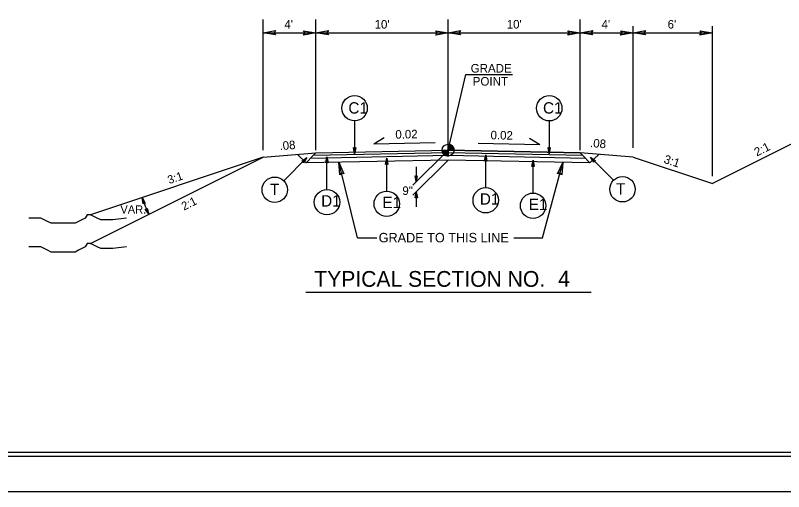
# Model space of a CAD drawing. Extents: x 573771 to 574316, y -53454 to -53190.
# Drawn here: x 574083 to 574199.3, y -53453.5 to -53381.4 of the extents above; entities that cross this region are included whole.
import ezdxf

# ---------------------------------------------------------------- set-up
doc = ezdxf.new("R2010")
doc.units = 0
for name, color, linetype in [('Sheet Cutting Line CELL', 7, 'Continuous'), ('Sheet Plot Border Inside CELL', 7, 'Continuous'), ('Sheet Plot Border Outside CELL', 7, 'Continuous'), ('Sheet Typical CELL', 7, 'Continuous'), ('Typical Grade Point Symbol CELL', 7, 'Continuous'), ('Typical ID Circle CELL', 7, 'Continuous'), ('Typical Pavement Slope CELL', 7, 'Continuous'), ('Typical Pavement Slope Information CELL', 7, 'Continuous'), ('Typical Shoulder Slope CELL', 7, 'Continuous'), ('Typical Shoulder Slope Information CELL', 7, 'Continuous'), ('Typical Slope Point Local CELL', 7, 'Continuous'), ('Typical Terminator CELL', 7, 'Continuous'), ('Typical Text General CELL', 7, 'Continuous'), ('Typical Text Grade Point CELL', 7, 'Continuous'), ('Typical Text ID Circle CELL', 7, 'Continuous'), ('Typical Text Label CELL', 7, 'Continuous')]:
    doc.layers.add(name, color=color, linetype=linetype)

msp = doc.modelspace()

# ---------------------------------------------------------------- linework, layer by layer
at = {"layer": 'Sheet Cutting Line CELL'}
msp.add_line((573911.95, -53453.54), (574316.11, -53453.54), dxfattribs=at)
at = {"layer": 'Sheet Plot Border Inside CELL'}
msp.add_lwpolyline([(574315.03, -53194.93), (573915.07, -53194.93), (573915.07, -53448.15), (574315.03, -53448.15)], close=True, dxfattribs=at)
at = {"layer": 'Sheet Plot Border Outside CELL'}
msp.add_lwpolyline([(574316.11, -53189.54), (573911.95, -53189.54), (573911.95, -53453.54), (574316.11, -53453.54)], close=True, dxfattribs=at)
at = {"layer": 'Sheet Typical CELL'}
msp.add_lwpolyline([(574312.03, -53195.54), (573952.03, -53195.54), (573952.03, -53447.54), (574312.03, -53447.54)], close=True, dxfattribs=at)
at = {"layer": 'Typical Grade Point Symbol CELL'}
for p, q in [((574148.51, -53401.82), (574148.51, -53400.93)), ((574147.62, -53401.82), (574148.51, -53401.82)), ((574149.41, -53401.82), (574148.51, -53401.82)), ((574148.51, -53402.72), (574148.51, -53401.82)), ((574148.51, -53401.82), (574148.51, -53402.72))]:
    msp.add_line(p, q, dxfattribs=at)
for points in [[(574148.52, -53400.93), (574148.52, -53400.93), (574148.52, -53401.82)], [(574148.54, -53400.93), (574148.54, -53401.82)], [(574148.56, -53400.93), (574148.56, -53401.82)], [(574148.57, -53400.93), (574148.57, -53401.82)], [(574148.59, -53400.93), (574148.59, -53401.82)], [(574148.61, -53400.93), (574148.61, -53401.82)], [(574148.63, -53400.93), (574148.63, -53401.82)], [(574148.64, -53400.94), (574148.64, -53401.82)], [(574148.66, -53400.94), (574148.66, -53401.82)], [(574148.68, -53400.94), (574148.68, -53401.82)], [(574148.7, -53400.95), (574148.7, -53401.82)], [(574148.72, -53400.95), (574148.72, -53401.82)], [(574148.73, -53400.95), (574148.73, -53401.82)], [(574148.75, -53400.96), (574148.75, -53401.82)], [(574148.77, -53400.96), (574148.77, -53401.82)], [(574148.79, -53400.97), (574148.79, -53401.82)], [(574148.81, -53400.98), (574148.81, -53401.82)], [(574148.82, -53400.98), (574148.82, -53401.82)], [(574148.84, -53400.99), (574148.84, -53401.82)], [(574148.86, -53401), (574148.86, -53401.82)], [(574148.88, -53401.01), (574148.88, -53401.82)], [(574148.9, -53401.01), (574148.9, -53401.82)], [(574148.91, -53401.02), (574148.91, -53401.82)], [(574148.93, -53401.03), (574148.93, -53401.82)], [(574148.95, -53401.04), (574148.95, -53401.82)], [(574148.97, -53401.05), (574148.97, -53401.82)], [(574148.98, -53401.06), (574148.98, -53401.82)], [(574149, -53401.07), (574149, -53401.82)], [(574149.02, -53401.09), (574149.02, -53401.82)], [(574149.04, -53401.1), (574149.04, -53401.82)], [(574149.06, -53401.11), (574149.06, -53401.82)], [(574149.07, -53401.12), (574149.07, -53401.82)], [(574149.09, -53401.14), (574149.09, -53401.82)], [(574149.11, -53401.16), (574149.11, -53401.82)], [(574149.13, -53401.17), (574149.13, -53401.82)], [(574149.15, -53401.19), (574149.15, -53401.82)], [(574149.16, -53401.21), (574149.16, -53401.82)], [(574149.18, -53401.23), (574149.18, -53401.82)], [(574149.2, -53401.25), (574149.2, -53401.82)], [(574149.22, -53401.27), (574149.22, -53401.82)], [(574149.24, -53401.3), (574149.24, -53401.82)], [(574149.25, -53401.32), (574149.25, -53401.82)], [(574149.27, -53401.35), (574149.27, -53401.82)], [(574149.29, -53401.38), (574149.29, -53401.82)], [(574149.31, -53401.41), (574149.31, -53401.82)], [(574149.33, -53401.45), (574149.33, -53401.82)], [(574147.62, -53401.82), (574147.62, -53401.92)], [(574147.64, -53401.82), (574147.64, -53402.02)], [(574147.66, -53401.82), (574147.66, -53402.09)], [(574147.67, -53401.82), (574147.67, -53402.14)], [(574147.69, -53401.82), (574147.69, -53402.18)], [(574147.71, -53401.82), (574147.71, -53402.22)], [(574147.73, -53401.82), (574147.73, -53402.25)], [(574147.75, -53401.82), (574147.75, -53402.29)], [(574147.76, -53401.82), (574147.76, -53402.31)], [(574147.78, -53401.82), (574147.78, -53402.34)], [(574147.8, -53401.82), (574147.8, -53402.36)], [(574147.82, -53401.82), (574147.82, -53402.39)], [(574147.84, -53401.82), (574147.84, -53402.41)], [(574147.85, -53401.82), (574147.85, -53402.43)], [(574147.87, -53401.82), (574147.87, -53402.45)], [(574147.89, -53401.82), (574147.89, -53402.47)], [(574147.91, -53401.82), (574147.91, -53402.48)], [(574147.92, -53401.82), (574147.92, -53402.5)], [(574147.94, -53401.82), (574147.94, -53402.51)], [(574147.96, -53401.82), (574147.96, -53402.53)], [(574147.98, -53401.82), (574147.98, -53402.54)], [(574148, -53401.82), (574148, -53402.55)], [(574148.01, -53401.82), (574148.01, -53402.56)], [(574148.03, -53401.82), (574148.03, -53402.58)], [(574148.05, -53401.82), (574148.05, -53402.59)], [(574148.07, -53401.82), (574148.07, -53402.6)], [(574148.09, -53401.82), (574148.09, -53402.61)], [(574148.1, -53401.82), (574148.1, -53402.62)], [(574148.12, -53401.82), (574148.12, -53402.63)], [(574148.14, -53401.82), (574148.14, -53402.63)], [(574148.16, -53401.82), (574148.16, -53402.64)], [(574148.18, -53401.82), (574148.18, -53402.65)], [(574148.19, -53401.82), (574148.19, -53402.66)], [(574148.21, -53401.82), (574148.21, -53402.66)], [(574148.23, -53401.82), (574148.23, -53402.67)], [(574148.25, -53401.82), (574148.25, -53402.68)], [(574148.26, -53401.82), (574148.26, -53402.68)], [(574148.28, -53401.82), (574148.28, -53402.69)], [(574148.3, -53401.82), (574148.3, -53402.69)], [(574148.32, -53401.82), (574148.32, -53402.69)], [(574148.34, -53401.82), (574148.34, -53402.7)], [(574148.35, -53401.82), (574148.35, -53402.7)], [(574148.37, -53401.82), (574148.37, -53402.7)], [(574148.39, -53401.82), (574148.39, -53402.71)], [(574148.41, -53401.82), (574148.41, -53402.71)], [(574148.43, -53401.82), (574148.43, -53402.71)], [(574148.44, -53401.82), (574148.44, -53402.71)], [(574148.46, -53401.82), (574148.46, -53402.71)], [(574148.48, -53401.82), (574148.48, -53402.72)], [(574148.5, -53401.82), (574148.5, -53402.72), (574148.5, -53402.72)], [(574149.34, -53401.49), (574149.34, -53401.82)], [(574149.36, -53401.54), (574149.36, -53401.82)], [(574149.38, -53401.6), (574149.38, -53401.82)], [(574149.4, -53401.69), (574149.4, -53401.82)]]:
    msp.add_lwpolyline(points, dxfattribs=at)
msp.add_circle((574148.51, -53401.82), 0.895, dxfattribs=at)
for start, end in [(359.9905, 89.9905), (179.9905, 269.9905)]:
    msp.add_arc((574148.51, -53401.82), 0.895, start, end, dxfattribs=at)
at = {"layer": 'Typical ID Circle CELL'}
for p, q in [((574134.36, -53397.4), (574134.36, -53402.37)), ((574163.82, -53397.4), (574163.82, -53402.37)), ((574154.2, -53407.5), (574154.2, -53402.52)), ((574123.63, -53406.46), (574127.15, -53402.95)), ((574130.18, -53407.79), (574130.18, -53402.82)), ((574139.22, -53408.03), (574139.22, -53403.06)), ((574161.37, -53408.32), (574161.37, -53403.35)), ((574173.55, -53406.39), (574170.04, -53402.88))]:
    msp.add_line(p, q, dxfattribs=at)
for centre in [(574134.36, -53395.47), (574163.82, -53395.48), (574122.27, -53407.82), (574174.91, -53407.75), (574130.18, -53409.71), (574139.22, -53409.95), (574154.2, -53409.42), (574161.37, -53410.24)]:
    msp.add_circle(centre, 1.92, dxfattribs=at)
at = {"layer": 'Typical Pavement Slope CELL'}
for p in [(574128.51, -53402.22), (574168.51, -53402.22)]:
    msp.add_line(p, (574148.51, -53401.82), dxfattribs=at)
at = {"layer": 'Typical Pavement Slope Information CELL'}
for p, q in [((574120.51, -53401.82), (574120.51, -53382.05)), ((574128.51, -53401.82), (574128.51, -53382.05)), ((574148.51, -53401.82), (574148.51, -53382.05)), ((574168.51, -53401.82), (574168.51, -53382.05)), ((574176.51, -53401.46), (574176.51, -53383.05)), ((574188.51, -53405.77), (574188.51, -53383.05)), ((574120.51, -53384.05), (574128.51, -53384.05)), ((574128.51, -53384.05), (574148.51, -53384.05)), ((574148.51, -53384.05), (574168.51, -53384.05)), ((574168.51, -53384.05), (574176.51, -53384.05)), ((574176.51, -53384.05), (574188.51, -53384.05)), ((574137.25, -53400.85), (574138.82, -53399.91)), ((574162.39, -53401.03), (574160.82, -53400.08)), ((574137.25, -53400.85), (574146.57, -53400.67)), ((574162.39, -53401.03), (574153.07, -53400.84)), ((574125.69, -53402.46), (574127.04, -53403.75)), ((574128.1, -53402.65), (574128.51, -53402.22)), ((574148.51, -53402.24), (574128.1, -53402.65)), ((574128.51, -53402.22), (574148.51, -53401.82)), ((574143.19, -53407.14), (574148.51, -53401.82)), ((574148.51, -53401.82), (574168.51, -53402.22)), ((574168.92, -53402.65), (574148.51, -53402.24)), ((574168.51, -53402.22), (574168.92, -53402.65)), ((574171.33, -53402.46), (574169.98, -53403.75)), ((574127.04, -53403.75), (574128.1, -53402.65)), ((574148.51, -53403.32), (574127.04, -53403.75)), ((574148.51, -53402.65), (574127.7, -53403.07)), ((574143.18, -53408.64), (574148.5, -53403.32)), ((574169.33, -53403.07), (574148.51, -53402.65)), ((574169.98, -53403.75), (574148.51, -53403.32)), ((574169.98, -53403.75), (574168.92, -53402.65)), ((574143.69, -53404.36), (574143.69, -53406.64)), ((574143.69, -53408.13), (574143.69, -53410.42))]:
    msp.add_line(p, q, dxfattribs=at)
at = {"layer": 'Typical Shoulder Slope CELL'}
for p, q in [((574120.51, -53402.89), (574128.51, -53402.22)), ((574176.51, -53402.89), (574168.51, -53402.22))]:
    msp.add_line(p, q, dxfattribs=at)
at = {"layer": 'Typical Slope Point Local CELL'}
for p, q in [((574204.42, -53398.93), (574188.51, -53406.89)), ((574094.38, -53415.96), (574120.51, -53402.89)), ((574120.51, -53402.89), (574094.38, -53411.6)), ((574176.51, -53402.89), (574188.51, -53406.89))]:
    msp.add_line(p, q, dxfattribs=at)
for points in [[(574099.82, -53412.12), (574097.75, -53412.38), (574097.23, -53412.38), (574096.45, -53412.38), (574095.93, -53412.38), (574095.41, -53412.12), (574094.9, -53411.86), (574094.38, -53411.6), (574093.86, -53411.6), (574093.6, -53412.12), (574093.08, -53412.38), (574092.56, -53412.64), (574092.04, -53412.9), (574091.52, -53412.9), (574091, -53412.9), (574090.49, -53412.9), (574089.97, -53412.9), (574089.45, -53412.9), (574088.93, -53412.9), (574088.41, -53412.9), (574087.89, -53412.64), (574087.37, -53412.38), (574086.86, -53412.12), (574086.08, -53412.12), (574085.56, -53412.12), (574085.04, -53412.12)], [(574099.82, -53416.48), (574097.75, -53416.73), (574097.23, -53416.73), (574096.45, -53416.73), (574095.93, -53416.73), (574095.41, -53416.48), (574094.9, -53416.22), (574094.38, -53415.96), (574093.86, -53415.96), (574093.6, -53416.48), (574093.08, -53416.73), (574092.56, -53416.99), (574092.04, -53417.25), (574091.52, -53417.25), (574091, -53417.25), (574090.49, -53417.25), (574089.97, -53417.25), (574089.45, -53417.25), (574088.93, -53417.25), (574088.41, -53417.25), (574087.89, -53416.99), (574087.37, -53416.73), (574086.86, -53416.48), (574086.08, -53416.48), (574085.56, -53416.48), (574085.04, -53416.48)]]:
    msp.add_lwpolyline(points, dxfattribs=at)
msp.add_arc((574120.51, -53402.89), 19.32, 198.4349, 206.5659, dxfattribs=at)
at = {"layer": 'Typical Terminator CELL'}
for points in [[(574122.39, -53384.38), (574120.51, -53384.05), (574122.4, -53383.72), (574122.16, -53384.05)], [(574126.64, -53383.73), (574128.51, -53384.05), (574126.63, -53384.39), (574126.87, -53384.05)], [(574130.39, -53384.38), (574128.51, -53384.05), (574130.4, -53383.72), (574130.16, -53384.05)], [(574146.64, -53383.73), (574148.51, -53384.05), (574146.63, -53384.39), (574146.87, -53384.05)], [(574150.39, -53384.38), (574148.51, -53384.05), (574150.4, -53383.72), (574150.16, -53384.05)], [(574166.64, -53383.73), (574168.51, -53384.05), (574166.63, -53384.39), (574166.87, -53384.05)], [(574170.39, -53384.38), (574168.51, -53384.05), (574170.4, -53383.72), (574170.16, -53384.05)], [(574174.64, -53383.73), (574176.51, -53384.05), (574174.63, -53384.39), (574174.87, -53384.05)], [(574178.39, -53384.38), (574176.51, -53384.05), (574178.4, -53383.72), (574178.16, -53384.05)], [(574186.64, -53383.73), (574188.51, -53384.05), (574186.63, -53384.39), (574186.87, -53384.05)], [(574134.52, -53401.43), (574134.36, -53402.37), (574134.2, -53401.42), (574134.36, -53401.54)], [(574163.98, -53401.44), (574163.82, -53402.37), (574163.65, -53401.43), (574163.82, -53401.55)], [(574154.04, -53403.46), (574154.2, -53402.52), (574154.36, -53403.47), (574154.2, -53403.35)], [(574126.37, -53403.5), (574127.15, -53402.95), (574126.6, -53403.73), (574126.57, -53403.53)], [(574130.02, -53403.76), (574130.18, -53402.82), (574130.35, -53403.76), (574130.18, -53403.64)], [(574132.11, -53405.55), (574131.97, -53403.65), (574132.75, -53405.4), (574132.37, -53405.25)], [(574139.06, -53404), (574139.22, -53403.06), (574139.38, -53404), (574139.22, -53403.88)], [(574161.21, -53404.29), (574161.37, -53403.35), (574161.54, -53404.29), (574161.37, -53404.17)], [(574165.08, -53405.39), (574165.88, -53403.67), (574165.71, -53405.58), (574165.45, -53405.26)], [(574170.58, -53403.66), (574170.04, -53402.88), (574170.82, -53403.43), (574170.62, -53403.46)], [(574143.85, -53405.71), (574143.69, -53406.64), (574143.52, -53405.7), (574143.69, -53405.82)], [(574143.53, -53409.07), (574143.69, -53408.13), (574143.86, -53409.07), (574143.69, -53408.95)], [(574102.33, -53409.94), (574102.19, -53409), (574102.64, -53409.84), (574102.45, -53409.78)], [(574102.96, -53410.62), (574103.23, -53411.53), (574102.66, -53410.76), (574102.87, -53410.79)]]:
    msp.add_lwpolyline(points, close=True, dxfattribs=at)
at = {"layer": 'Typical Text Grade Point CELL'}
for p, q in [((574148.51, -53401.82), (574151.2, -53390.39)), ((574151.2, -53390.39), (574158.28, -53390.39)), ((574134.82, -53415.09), (574131.97, -53403.65)), ((574162.8, -53415.09), (574165.88, -53403.67)), ((574134.82, -53415.09), (574137.74, -53415.09)), ((574158.45, -53415.09), (574162.8, -53415.09))]:
    msp.add_line(p, q, dxfattribs=at)
at = {"layer": 'Typical Text Label CELL'}
msp.add_line((574126.98, -53423.32), (574170.19, -53423.32), dxfattribs=at)

# ---------------------------------------------------------------- texts
at = {"layer": 'Typical Pavement Slope Information CELL'}
for s, p in [("4'", (574123.74, -53383.41)), ("10'", (574137.39, -53383.41)), ("10'", (574157.39, -53383.41)), ("4'", (574171.74, -53383.41)), ("6'", (574181.74, -53383.41)), ('9"', (574141.59, -53408.61))]:
    msp.add_text(s, height=1.295, dxfattribs=at).set_placement(p)
for s, rotation, p in [('0.02 ', 1.1457, (574140.54, -53400.09)), ('0.02', 358.8543, (574154.93, -53400.18)), ('2:1', 26.5651, (574195.24, -53402.8)), ('3:1', 341.5651, (574181.05, -53403.72))]:
    msp.add_text(s, height=1.295, rotation=rotation, dxfattribs=at).set_placement(p)
at = {"layer": 'Typical Shoulder Slope Information CELL'}
for rotation, p in [(355.2393, (574169.96, -53401.35)), (4.7607, (574123.05, -53401.84))]:
    msp.add_text('.08', height=1.295, rotation=rotation, dxfattribs=at).set_placement(p)
at = {"layer": 'Typical Slope Point Local CELL'}
for s, rotation, p in [('3:1', 18.4349, (574106.29, -53406.97)), ('2:1', 26.5659, (574108.53, -53410.98))]:
    msp.add_text(s, height=1.25, rotation=rotation, dxfattribs=at).set_placement(p)
msp.add_text('VAR.', height=1.25, dxfattribs=at).set_placement((574098.91, -53411.43))
at = {"layer": 'Typical Text General CELL'}
msp.add_text('GRADE TO THIS LINE', height=1.4323, dxfattribs=at).set_placement((574138, -53415.79))
at = {"layer": 'Typical Text Grade Point CELL'}
for s, p in [('GRADE', (574151.93, -53390.08)), ('POINT', (574152.24, -53392.05))]:
    msp.add_text(s, height=1.305, dxfattribs=at).set_placement(p)
at = {"layer": 'Typical Text ID Circle CELL'}
for s, p in [('C1', (574133.42, -53396.29)), ('C1', (574162.88, -53396.29)), ('T ', (574121.56, -53408.62)), ('T ', (574173.92, -53408.55)), ('D1', (574153.32, -53410.08)), ('D1', (574129.3, -53410.37)), ('E1', (574138.58, -53410.61)), ('E1', (574160.73, -53410.9))]:
    msp.add_text(s, height=1.722, dxfattribs=at).set_placement(p)
at = {"layer": 'Typical Text Label CELL'}
for s, height, p in [('TYPICAL SECTION NO.  ', 2.3871, (574128.26, -53422.52)), ('4', 2.39, (574165.16, -53422.49))]:
    msp.add_text(s, height=height, dxfattribs=at).set_placement(p)

doc.saveas('drawing.dxf')
